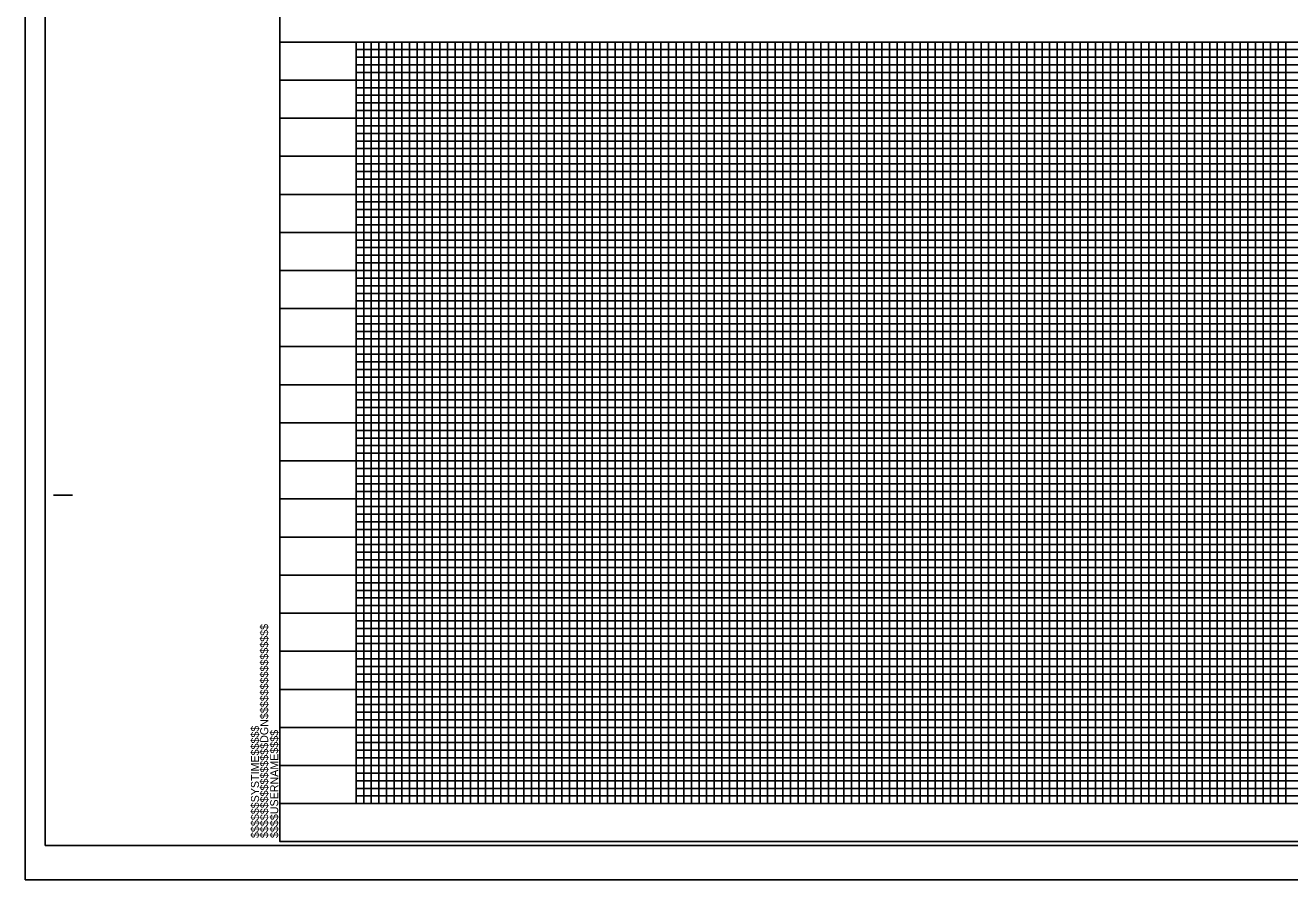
# Model space of a CAD drawing. Extents: x 2044835 to 2046519, y 755505 to 756605.
# Drawn here: x 2044835 to 2045664, y 755505 to 756066 of the extents above; entities that cross this region are included whole.
import ezdxf

# ---------------------------------------------------------------- set-up
doc = ezdxf.new("R2010")
doc.units = 0
for name, color, linetype in [('Sheet Cutting Line CELL', 7, 'Continuous'), ('Sheet DOT Grid CELL', 7, 'Continuous'), ('Sheet Layout Profile Border Port 2', 7, 'Continuous'), ('Sheet Plot Border Inside CELL', 7, 'Continuous'), ('Sheet Plot Border Outside CELL', 7, 'Continuous'), ('Sheet Profile CELL', 7, 'Continuous'), ('Sheet Profile Grid Major CELL', 7, 'Continuous'), ('Sheet Profile Grid Middle CELL', 7, 'Continuous'), ('Sheet Profile Grid Minor CELL', 7, 'Continuous')]:
    doc.layers.add(name, color=color, linetype=linetype)

msp = doc.modelspace()

# ---------------------------------------------------------------- linework, layer by layer
at = {"layer": 'Sheet Cutting Line CELL'}
for p, q in [((2044834.63, 756605.41), (2044834.63, 755505.41)), ((2044834.63, 755505.41), (2046518.63, 755505.41))]:
    msp.add_line(p, q, dxfattribs=at)
at = {"layer": 'Sheet DOT Grid CELL'}
for p, q in [((2045001.63, 756055.41), (2046501.52, 756055.41)), ((2045051.63, 756055.41), (2045051.63, 755555.41)), ((2045101.63, 756055.41), (2045101.63, 755555.41)), ((2045151.63, 756055.41), (2045151.63, 755555.41)), ((2045201.63, 756055.41), (2045201.63, 755555.41)), ((2045251.63, 756055.41), (2045251.63, 755555.41)), ((2045301.63, 756055.41), (2045301.63, 755555.41)), ((2045351.63, 756055.41), (2045351.63, 755555.41)), ((2045401.63, 756055.41), (2045401.63, 755555.41)), ((2045451.63, 756055.41), (2045451.63, 755555.41)), ((2045501.63, 756055.41), (2045501.63, 755555.41)), ((2045551.63, 756055.41), (2045551.63, 755555.41)), ((2045601.63, 756055.41), (2045601.63, 755555.41)), ((2045651.63, 756055.41), (2045651.63, 755555.41)), ((2045001.63, 756005.41), (2046501.52, 756005.41)), ((2045001.63, 755955.41), (2046501.52, 755955.41)), ((2045001.63, 755905.41), (2046501.52, 755905.41)), ((2045001.63, 755855.41), (2046501.52, 755855.41)), ((2045001.63, 755805.41), (2046501.52, 755805.41)), ((2045001.63, 755755.41), (2046501.52, 755755.41)), ((2045001.63, 755705.41), (2046501.52, 755705.41)), ((2045001.63, 755655.41), (2046501.52, 755655.41)), ((2045001.63, 755605.41), (2046501.52, 755605.41))]:
    msp.add_line(p, q, dxfattribs=at)
at = {"layer": 'Sheet Layout Profile Border Port 2'}
msp.add_lwpolyline([(2045051.63, 756055.41), (2046451.63, 756055.41), (2046451.63, 755555.41), (2045051.63, 755555.41)], close=True, dxfattribs=at)
at = {"layer": 'Sheet Plot Border Inside CELL'}
msp.add_lwpolyline([(2044847.63, 755527.86), (2046514.13, 755527.86), (2046514.13, 756582.96), (2044847.63, 756582.96)], close=True, dxfattribs=at)
at = {"layer": 'Sheet Plot Border Outside CELL'}
msp.add_lwpolyline([(2044834.63, 755505.41), (2046518.63, 755505.41), (2046518.63, 756605.41), (2044834.63, 756605.41)], close=True, dxfattribs=at)
at = {"layer": 'Sheet Profile CELL'}
for p, q in [((2045001.63, 756055.41), (2046501.63, 756055.41)), ((2044853.13, 755757.91), (2044865.63, 755757.91)), ((2046501.63, 755555.41), (2045001.63, 755555.41)), ((2045001.63, 755530.41), (2046501.63, 755530.41)), ((2045001.63, 755530.41), (2045001.63, 755530.41)), ((2045001.63, 755530.41), (2045001.63, 755530.41)), ((2045001.63, 755530.41), (2045001.63, 755530.41)), ((2045001.63, 755530.41), (2045001.63, 755530.41)), ((2045001.63, 755530.41), (2045001.63, 755530.41)), ((2045001.63, 755530.41), (2045001.63, 755530.41)), ((2045001.63, 755530.41), (2045001.63, 755530.41))]:
    msp.add_line(p, q, dxfattribs=at)
msp.add_lwpolyline([(2046501.63, 756580.41), (2045001.63, 756580.41), (2045001.63, 755530.41), (2046501.63, 755530.41)], close=True, dxfattribs=at)
msp.add_lwpolyline([(2045039.13, 755530.41), (2045039.13, 755530.41)], dxfattribs=at)
at = {"layer": 'Sheet Profile Grid Major CELL'}
for p, q in [((2045501.63, 756055.41), (2045551.63, 756055.41)), ((2045601.63, 756055.41), (2045651.63, 756055.41)), ((2045001.63, 755555.41), (2045001.63, 755555.41))]:
    msp.add_line(p, q, dxfattribs=at)
for points in [[(2045051.63, 756055.41), (2045051.63, 755555.41), (2045101.63, 755555.41), (2045101.63, 756055.41), (2045151.63, 756055.41), (2045151.63, 755555.41), (2045201.63, 755555.41), (2045201.63, 756055.41), (2045251.63, 756055.41), (2045251.63, 755555.41), (2045301.63, 755555.41), (2045301.63, 756055.41), (2045351.63, 756055.41), (2045351.63, 755555.41), (2045401.63, 755555.41), (2045401.63, 756055.41), (2045451.63, 756055.41), (2045451.63, 755555.41), (2045501.63, 755555.41), (2045501.63, 756055.41), (2045551.63, 756055.41), (2045551.63, 755555.41), (2045601.63, 755555.41), (2045601.63, 756055.41), (2045651.63, 756055.41), (2045651.63, 755555.41), (2045701.63, 755555.41)], [(2046501.63, 756005.41), (2045001.63, 756005.41)], [(2046501.63, 755955.41), (2045001.63, 755955.41), (2045001.63, 755905.41), (2046501.63, 755905.41)], [(2046501.63, 755855.41), (2045001.63, 755855.41), (2045001.63, 755805.41), (2046501.63, 755805.41)], [(2046501.63, 755755.41), (2045001.63, 755755.41), (2045001.63, 755705.41), (2046501.63, 755705.41)], [(2046501.63, 755655.41), (2045001.63, 755655.41), (2045001.63, 755655.41), (2045001.63, 755605.41), (2046501.63, 755605.41)], [(2046501.63, 755555.41), (2045001.63, 755555.41)]]:
    msp.add_lwpolyline(points, dxfattribs=at)
at = {"layer": 'Sheet Profile Grid Middle CELL'}
for points in [[(2045026.63, 756055.41), (2045076.63, 756055.41), (2045076.63, 755555.41), (2045126.63, 755555.41), (2045126.63, 756055.41), (2045176.63, 756055.41), (2045176.63, 755555.41), (2045226.63, 755555.41), (2045226.63, 756055.41), (2045276.63, 756055.41), (2045276.63, 755555.41), (2045326.63, 755555.41), (2045326.63, 756055.41), (2045376.63, 756055.41), (2045376.63, 755555.41), (2045426.63, 755555.41), (2045426.63, 756055.41), (2045476.63, 756055.41), (2045476.63, 755555.41), (2045526.63, 755555.41), (2045526.63, 756055.41), (2045576.63, 756055.41), (2045576.63, 755555.41), (2045626.63, 755555.41), (2045626.63, 755555.41), (2045626.63, 756055.41), (2045676.63, 756055.41)], [(2045001.63, 756030.41), (2046501.63, 756030.41)], [(2046501.63, 755980.41), (2045001.63, 755980.41), (2045001.63, 755930.41), (2046501.63, 755930.41)], [(2046501.63, 755880.41), (2045001.63, 755880.41), (2045001.63, 755830.41), (2046501.63, 755830.41)], [(2046501.63, 755780.41), (2045001.63, 755780.41), (2045001.63, 755730.41), (2046501.63, 755730.41)], [(2046501.63, 755680.41), (2045001.63, 755680.41), (2045001.63, 755630.41), (2046501.63, 755630.41)], [(2046501.63, 755580.41), (2045001.63, 755580.41)]]:
    msp.add_lwpolyline(points, dxfattribs=at)
at = {"layer": 'Sheet Profile Grid Minor CELL'}
for p, q in [((2045051.63, 756050.41), (2046451.63, 756050.41)), ((2046451.63, 756045.41), (2045051.63, 756045.41)), ((2045051.63, 756040.41), (2046451.63, 756040.41)), ((2046451.63, 756035.41), (2045051.63, 756035.41)), ((2045051.63, 756025.41), (2046451.63, 756025.41)), ((2046451.63, 756020.41), (2045051.63, 756020.41)), ((2045051.63, 756015.41), (2046451.63, 756015.41)), ((2046451.63, 756010.41), (2045051.63, 756010.41)), ((2045051.63, 756000.41), (2046451.63, 756000.41)), ((2046451.63, 755995.41), (2045051.63, 755995.41)), ((2045051.63, 755990.41), (2046451.63, 755990.41)), ((2046451.63, 755985.41), (2045051.63, 755985.41)), ((2045051.63, 755975.41), (2046451.63, 755975.41)), ((2046451.63, 755970.41), (2045051.63, 755970.41)), ((2045051.63, 755965.41), (2046451.63, 755965.41)), ((2046451.63, 755960.41), (2045051.63, 755960.41)), ((2045051.63, 755950.41), (2046451.63, 755950.41)), ((2046451.63, 755945.41), (2045051.63, 755945.41)), ((2045051.63, 755940.41), (2046451.63, 755940.41)), ((2046451.63, 755935.41), (2045051.63, 755935.41)), ((2045051.63, 755925.41), (2046451.63, 755925.41)), ((2046451.63, 755920.41), (2045051.63, 755920.41)), ((2045051.63, 755915.41), (2046451.63, 755915.41)), ((2046451.63, 755910.41), (2045051.63, 755910.41)), ((2045051.63, 755900.41), (2046451.63, 755900.41)), ((2046451.63, 755895.41), (2045051.63, 755895.41)), ((2045051.63, 755890.41), (2046451.63, 755890.41)), ((2046451.63, 755885.41), (2045051.63, 755885.41)), ((2045051.63, 755875.41), (2046451.63, 755875.41)), ((2046451.63, 755870.41), (2045051.63, 755870.41)), ((2045051.63, 755865.41), (2046451.63, 755865.41)), ((2046451.63, 755860.41), (2045051.63, 755860.56)), ((2045051.63, 755850.41), (2046451.63, 755850.41)), ((2046451.63, 755845.41), (2045051.63, 755845.41)), ((2045051.63, 755840.41), (2046451.63, 755840.41)), ((2046451.63, 755835.41), (2045051.63, 755835.41)), ((2045051.63, 755825.41), (2046451.63, 755825.41)), ((2046451.63, 755820.41), (2045051.63, 755820.41)), ((2045051.63, 755815.41), (2046451.63, 755815.41)), ((2046451.63, 755810.41), (2045051.63, 755810.41)), ((2045051.63, 755800.41), (2046451.63, 755800.41)), ((2046451.63, 755795.41), (2045051.63, 755795.41)), ((2045051.63, 755790.41), (2046451.63, 755790.41)), ((2046451.63, 755785.41), (2045051.63, 755785.41)), ((2045051.63, 755775.41), (2046451.63, 755775.41)), ((2046451.63, 755770.41), (2045051.63, 755770.41)), ((2045051.63, 755765.41), (2046451.63, 755765.41)), ((2046451.63, 755760.41), (2045051.63, 755760.41)), ((2045051.63, 755750.41), (2046451.63, 755750.41)), ((2046451.63, 755745.41), (2045051.63, 755745.41)), ((2045051.63, 755740.41), (2046451.63, 755740.41)), ((2046451.63, 755735.41), (2045051.63, 755735.41)), ((2045051.63, 755725.41), (2046451.63, 755725.41)), ((2046451.63, 755720.41), (2045051.63, 755720.41)), ((2045051.63, 755715.41), (2046451.63, 755715.41)), ((2046451.63, 755710.41), (2045051.63, 755710.41)), ((2045051.63, 755700.41), (2046451.63, 755700.41)), ((2046451.63, 755695.41), (2045051.63, 755695.41)), ((2045051.63, 755690.41), (2046451.63, 755690.41)), ((2046451.63, 755685.41), (2045051.63, 755685.41)), ((2045051.63, 755675.41), (2046451.63, 755675.41)), ((2046451.63, 755670.41), (2045051.63, 755670.41)), ((2045051.63, 755665.41), (2046451.63, 755665.41)), ((2046451.63, 755660.41), (2045051.63, 755660.41)), ((2045051.63, 755650.41), (2046451.63, 755650.41)), ((2046451.63, 755645.41), (2045051.63, 755645.41)), ((2045051.63, 755640.41), (2046451.63, 755640.41)), ((2046451.63, 755635.41), (2045051.63, 755635.41)), ((2045051.63, 755625.41), (2046451.63, 755625.41)), ((2046451.63, 755620.41), (2045051.63, 755620.41)), ((2045051.63, 755615.41), (2046451.63, 755615.41)), ((2046451.63, 755610.41), (2045051.63, 755610.41)), ((2045051.63, 755600.41), (2046451.63, 755600.41)), ((2046451.63, 755595.41), (2045051.63, 755595.41)), ((2045051.63, 755590.41), (2046451.63, 755590.41)), ((2046451.63, 755585.41), (2045051.63, 755585.41)), ((2045051.63, 755575.41), (2046451.63, 755575.41)), ((2046451.63, 755570.41), (2045051.63, 755570.41)), ((2045051.63, 755565.41), (2046451.63, 755565.41)), ((2045051.63, 755560.41), (2046451.63, 755560.41))]:
    msp.add_line(p, q, dxfattribs=at)
for points in [[(2045051.63, 756055.41), (2045056.63, 756055.41), (2045056.63, 755555.41), (2045061.63, 755555.41), (2045061.63, 756055.41), (2045066.63, 756055.41), (2045066.63, 755555.41), (2045071.63, 755555.41), (2045071.63, 756055.41), (2045081.63, 756055.41), (2045081.63, 755555.41), (2045086.63, 755555.41), (2045086.63, 756055.41), (2045091.63, 756055.41), (2045091.63, 755555.41), (2045096.63, 755555.41), (2045106.63, 755555.41), (2045111.63, 755555.41), (2045111.63, 756055.41), (2045116.63, 756055.41), (2045116.63, 755555.41), (2045121.63, 755555.41), (2045121.63, 756055.41), (2045131.63, 756055.41), (2045131.63, 755555.41), (2045136.63, 755555.41), (2045136.63, 756055.41), (2045141.63, 756055.41), (2045141.63, 755555.41), (2045146.63, 755555.41), (2045146.63, 756055.41), (2045156.63, 756055.41), (2045156.63, 755555.41), (2045161.63, 755555.41), (2045161.63, 756055.41), (2045166.63, 756055.41), (2045166.63, 755555.41), (2045171.63, 755555.41), (2045171.63, 756055.41), (2045181.63, 756055.41), (2045181.63, 755555.41), (2045186.63, 755555.41), (2045186.63, 756055.41), (2045191.63, 756055.41), (2045191.63, 755555.41), (2045196.63, 755555.41), (2045196.63, 756055.41), (2045206.63, 756055.41), (2045206.63, 755555.41), (2045211.63, 755555.41), (2045211.63, 756055.41), (2045216.63, 756055.41), (2045216.63, 755555.41), (2045221.63, 755555.41), (2045221.63, 756055.41), (2045231.63, 756055.41), (2045231.63, 755555.41), (2045236.63, 755555.41), (2045236.63, 756055.41), (2045241.63, 756055.41), (2045241.63, 755555.41), (2045246.63, 755555.41), (2045246.63, 756055.41), (2045256.63, 756055.41), (2045256.63, 755555.41), (2045261.63, 755555.41), (2045261.63, 756055.41), (2045266.63, 756055.41), (2045266.63, 755555.41)], [(2045096.63, 755555.41), (2045096.63, 756055.41), (2045106.63, 756055.41), (2045106.63, 755555.41)], [(2045266.63, 755555.41), (2045271.63, 755555.41), (2045271.63, 756055.41), (2045281.63, 756055.41), (2045281.63, 755555.41), (2045286.63, 755555.41), (2045286.63, 756055.41), (2045291.63, 756055.41), (2045291.63, 755555.41), (2045296.63, 755555.41), (2045296.63, 756055.41), (2045306.63, 756055.41), (2045306.63, 755555.41), (2045311.63, 755555.41), (2045311.63, 756055.41), (2045316.63, 756055.41), (2045316.63, 755555.41), (2045321.63, 755555.41), (2045321.63, 756055.41), (2045331.63, 756055.41), (2045331.63, 755555.41), (2045336.63, 755555.41), (2045336.63, 756055.41), (2045341.63, 756055.41), (2045341.63, 755555.41), (2045346.63, 755555.41), (2045346.63, 756055.41), (2045356.63, 756055.41), (2045356.63, 755555.41), (2045361.63, 755555.41), (2045361.63, 756055.41), (2045366.63, 756055.41), (2045366.63, 755555.41), (2045371.63, 755555.41), (2045371.63, 756055.41), (2045381.63, 756055.41), (2045381.63, 755555.41), (2045386.63, 755555.41), (2045386.63, 756055.41), (2045391.63, 756055.41), (2045391.63, 755555.41), (2045396.63, 755555.41), (2045396.63, 756055.41), (2045406.63, 756055.41), (2045406.63, 755555.41), (2045411.63, 755555.41), (2045411.63, 756055.41), (2045416.63, 756055.41), (2045416.63, 755555.41), (2045421.63, 755555.41), (2045421.63, 756055.41), (2045431.63, 756055.41), (2045431.63, 755555.41), (2045436.63, 755555.41), (2045436.63, 756055.41), (2045441.63, 756055.41), (2045441.63, 755555.41), (2045446.63, 755555.41), (2045446.63, 756055.41), (2045456.63, 756055.41), (2045456.63, 755555.41), (2045461.63, 755555.41), (2045461.63, 756055.41), (2045466.63, 756055.41), (2045466.63, 755555.41), (2045471.63, 755555.41), (2045471.63, 756055.41), (2045481.63, 756055.41), (2045481.63, 755555.41), (2045486.63, 755555.41), (2045486.63, 756055.41), (2045491.63, 756055.41), (2045491.63, 755555.41), (2045496.63, 755555.41), (2045496.63, 756055.41), (2045506.63, 756055.41), (2045506.63, 755555.41), (2045511.63, 755555.41), (2045511.63, 756055.41), (2045516.63, 756055.41), (2045516.63, 755555.41), (2045521.63, 755555.41), (2045521.63, 756055.41), (2045531.63, 756055.41), (2045531.63, 755555.41), (2045536.63, 755555.41), (2045536.63, 756055.41), (2045541.63, 756055.41), (2045541.63, 755555.41), (2045546.63, 755555.41), (2045546.63, 756055.41), (2045556.63, 756055.41), (2045556.63, 755555.41), (2045561.63, 755555.41), (2045561.63, 756055.41), (2045566.63, 756055.41), (2045566.63, 755555.41), (2045571.63, 755555.41), (2045571.63, 756055.41), (2045581.63, 756055.41)], [(2045581.63, 756055.41), (2045581.63, 755555.41), (2045586.63, 755555.41), (2045586.63, 756055.41), (2045591.63, 756055.41), (2045591.63, 755555.41), (2045596.63, 755555.41), (2045596.63, 756055.41), (2045606.63, 756055.41), (2045606.63, 755555.41), (2045611.63, 755555.41), (2045611.63, 756055.41), (2045616.63, 756055.41), (2045616.63, 755555.41), (2045621.63, 755555.41), (2045621.63, 756055.41), (2045631.63, 756055.41), (2045631.63, 755555.41), (2045636.63, 755555.41), (2045636.63, 756055.41), (2045641.63, 756055.41), (2045641.63, 755555.41), (2045646.63, 755555.41), (2045646.63, 756055.41), (2045656.63, 756055.41), (2045656.63, 755555.41), (2045661.63, 755555.41), (2045661.63, 756055.41), (2045666.63, 756055.41)]]:
    msp.add_lwpolyline(points, dxfattribs=at)

# ---------------------------------------------------------------- texts
at = {"layer": 'Sheet Profile CELL'}
for s, p in [('$$$$$$$$$$$$$$$$DGN$$$$$$$$$$$$$$$$', (2044994, 755532.79)), ('$$$$$$SYSTIME$$$$$', (2044987.95, 755532.79)), ('$$$$USERNAME$$$$', (2045000.57, 755532.8))]:
    msp.add_text(s, height=5.25, rotation=90, dxfattribs=at).set_placement(p)

doc.saveas('drawing.dxf')
